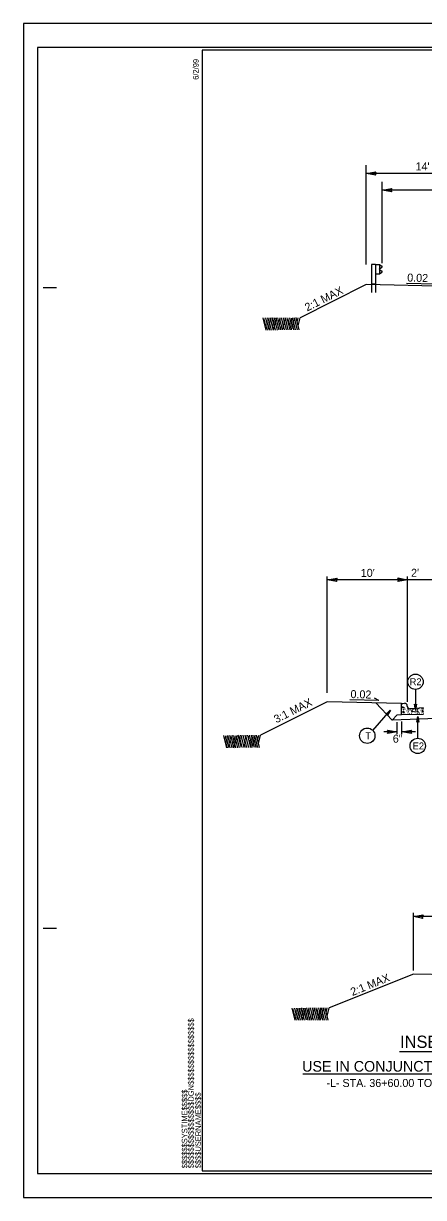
# Model space of a CAD drawing. Extents: x 573748 to 574632, y -54663 to -53209.
# Drawn here: x 573944.2 to 574019, y -53898.7 to -53678.7 of the extents above; entities that cross this region are included whole.
import ezdxf

# ---------------------------------------------------------------- set-up
doc = ezdxf.new("R2010")
doc.units = 0
for name, color, linetype in [('Prop Dimension', 7, 'Continuous'), ('Prop Dimension Text', 7, 'Continuous'), ('Prop Terminator CELL', 7, 'Continuous'), ('Sheet Cutting Line CELL', 7, 'Continuous'), ('Sheet Plot Border Inside CELL', 7, 'Continuous'), ('Sheet Plot Border Outside CELL', 7, 'Continuous'), ('Sheet Typical CELL', 7, 'Continuous'), ('Typical Arrow Superelevation CELL', 7, 'Continuous'), ('Typical Curb CELL', 7, 'Continuous'), ('Typical Guardrail CELL', 7, 'Continuous'), ('Typical Hinge Slope Arterial CELL', 7, 'Continuous'), ('Typical ID Circle CELL', 7, 'Continuous'), ('Typical Pavement Slope CELL', 7, 'Continuous'), ('Typical Slope Point Local CELL', 7, 'Continuous'), ('Typical Terminator CELL', 7, 'Continuous'), ('Typical Text General CELL', 7, 'Continuous'), ('Typical Text ID Circle CELL', 7, 'Continuous'), ('Typical Text Label CELL', 7, 'Continuous')]:
    doc.layers.add(name, color=color, linetype=linetype)

msp = doc.modelspace()

# ---------------------------------------------------------------- linework, layer by layer
at = {"layer": 'Prop Dimension'}
for p, q in [((574008.28, -53723.83), (574008.28, -53705.24)), ((574029.28, -53706.77), (574008.28, -53706.77)), ((574011.28, -53723.58), (574011.28, -53708.38)), ((574029.28, -53709.91), (574011.28, -53709.91)), ((574001.02, -53804.13), (574001.02, -53782.34)), ((574016.02, -53782.93), (574001.02, -53782.93)), ((574016.02, -53805.77), (574016.02, -53782.34)), ((574033.05, -53782.93), (574016.02, -53782.93)), ((574014.09, -53811.84), (574014.09, -53809.63)), ((574014.98, -53811.84), (574014.98, -53809.48)), ((574014.09, -53811.41), (574011.58, -53811.41)), ((574017.49, -53811.41), (574014.98, -53811.41)), ((574017.12, -53856.17), (574017.12, -53845.31)), ((574029.34, -53846.04), (574017.12, -53846.04))]:
    msp.add_line(p, q, dxfattribs=at)
at = {"layer": 'Prop Terminator CELL'}
for points in [[(574010.07, -53707.1), (574008.28, -53706.77), (574010.09, -53706.47), (574009.86, -53706.79)], [(574013.07, -53710.24), (574011.28, -53709.91), (574013.09, -53709.61), (574012.86, -53709.93)], [(574002.82, -53783.26), (574001.02, -53782.93), (574002.84, -53782.63), (574002.6, -53782.95)], [(574014.23, -53782.59), (574016.02, -53782.93), (574014.21, -53783.22), (574014.44, -53782.91)], [(574012.29, -53811.08), (574014.09, -53811.41), (574012.27, -53811.71), (574012.51, -53811.39)], [(574016.78, -53811.75), (574014.98, -53811.41), (574016.79, -53811.12), (574016.56, -53811.43)], [(574018.92, -53846.37), (574017.12, -53846.04), (574018.94, -53845.74), (574018.7, -53846.06)]]:
    msp.add_lwpolyline(points, close=True, dxfattribs=at)
at = {"layer": 'Sheet Cutting Line CELL'}
for p, q in [((574280.97, -53678.68), (573944.17, -53678.68)), ((573944.17, -53678.68), (573944.17, -53898.68)), ((573944.17, -53898.68), (574280.97, -53898.68))]:
    msp.add_line(p, q, dxfattribs=at)
at = {"layer": 'Sheet Plot Border Inside CELL'}
msp.add_lwpolyline([(574280.07, -53683.17), (573946.77, -53683.17), (573946.77, -53894.19), (574280.07, -53894.19)], close=True, dxfattribs=at)
at = {"layer": 'Sheet Plot Border Outside CELL'}
msp.add_lwpolyline([(574280.97, -53678.68), (573944.17, -53678.68), (573944.17, -53898.68), (574280.97, -53898.68)], close=True, dxfattribs=at)
at = {"layer": 'Sheet Typical CELL'}
for p, q in [((573947.87, -53728.18), (573950.37, -53728.18)), ((573947.87, -53848.18), (573950.37, -53848.18)), ((573977.57, -53893.68), (573977.57, -53893.68)), ((573977.57, -53893.68), (573977.57, -53893.68)), ((573977.57, -53893.68), (573977.57, -53893.68)), ((573977.57, -53893.68), (573977.57, -53893.68)), ((573977.57, -53893.68), (573977.57, -53893.68)), ((573977.57, -53893.68), (573977.57, -53893.68))]:
    msp.add_line(p, q, dxfattribs=at)
msp.add_lwpolyline([(574277.57, -53683.68), (573977.57, -53683.68), (573977.57, -53893.68), (574277.57, -53893.68)], close=True, dxfattribs=at)
msp.add_lwpolyline([(573985.07, -53893.68), (573985.07, -53893.68)], dxfattribs=at)
at = {"layer": 'Typical Arrow Superelevation CELL'}
for p, q in [((574021.25, -53727.53), (574015.86, -53727.38)), ((574010.63, -53805.57), (574009.85, -53805.1)), ((574010.63, -53805.57), (574005.24, -53805.43))]:
    msp.add_line(p, q, dxfattribs=at)
at = {"layer": 'Typical Curb CELL'}
for p, q in [((574014.92, -53806.1), (574015.47, -53806.08)), ((574014.92, -53808.19), (574014.92, -53806.1)), ((574015.02, -53806.89), (574015.34, -53806.78)), ((574015.31, -53806.97), (574015.02, -53806.89)), ((574015.3, -53807.55), (574015.09, -53807.71)), ((574015.44, -53807.78), (574015.3, -53807.55)), ((574015.34, -53806.78), (574015.31, -53806.97)), ((574015.99, -53806.59), (574015.99, -53806.57)), ((574019.02, -53806.91), (574016.52, -53807.08)), ((574016.85, -53807.39), (574016.79, -53807.63)), ((574017.04, -53807.63), (574016.85, -53807.39)), ((574017.92, -53807.48), (574017.71, -53807.64)), ((574018.06, -53807.72), (574017.92, -53807.48)), ((574018.8, -53807.37), (574018.74, -53807.61)), ((574018.99, -53807.62), (574018.8, -53807.37)), ((574014.09, -53808.21), (574014.92, -53808.19)), ((574014.92, -53808.19), (574019.02, -53808.09)), ((574015.09, -53807.71), (574015.44, -53807.78)), ((574016.79, -53807.63), (574017.04, -53807.63)), ((574017.71, -53807.64), (574018.06, -53807.72)), ((574018.74, -53807.61), (574018.99, -53807.62))]:
    msp.add_line(p, q, dxfattribs=at)
for centre in [(574014.96, -53806.33), (574015.08, -53806.71), (574015.29, -53807.27), (574015.41, -53806.24), (574015.54, -53807.16), (574015.92, -53807.5), (574016.08, -53807.09), (574016.12, -53807.19), (574016.19, -53807.55), (574016.49, -53807.36), (574016.55, -53807.15), (574016.96, -53807.22), (574017.16, -53807.1), (574017.39, -53807.29), (574017.5, -53807.22), (574017.55, -53807.42), (574017.91, -53807.2), (574018.16, -53807.09), (574018.54, -53807.43), (574018.7, -53807.02), (574018.74, -53807.12), (574018.97, -53807.15), (574015.28, -53808.09), (574015.64, -53807.99), (574016.01, -53808.12), (574016.12, -53807.87), (574016.37, -53808.05), (574016.8, -53807.99), (574017.14, -53808.12), (574017.23, -53807.63), (574017.43, -53807.72), (574017.57, -53808.06), (574017.9, -53808.02), (574018.25, -53807.93), (574018.63, -53808.05), (574018.74, -53807.81), (574018.98, -53807.98)]:
    msp.add_circle(centre, 0.0168, dxfattribs=at)
for centre, start, end in [((574015.48, -53806.58), 1.4804, 91.4804), ((574016.49, -53806.58), 181.4804, 273.8649)]:
    msp.add_arc(centre, 0.502, start, end, dxfattribs=at)
at = {"layer": 'Typical Guardrail CELL'}
for p, q in [((574010.05, -53723.83), (574009.3, -53723.83)), ((574009.3, -53723.83), (574009.3, -53727.56)), ((574010.05, -53723.83), (574010.05, -53727.56)), ((574010.05, -53723.83), (574010.79, -53723.83)), ((574010.79, -53723.83), (574010.79, -53725.57)), ((574010.79, -53723.83), (574011.23, -53724.14)), ((574010.05, -53725.57), (574010.79, -53725.57)), ((574010.79, -53724.63), (574011.23, -53724.33)), ((574010.79, -53724.7), (574010.79, -53724.63)), ((574010.79, -53724.7), (574010.79, -53724.77)), ((574010.79, -53724.77), (574011.23, -53725.08)), ((574010.79, -53725.57), (574011.23, -53725.27)), ((574010.05, -53727.56), (574009.3, -53727.56)), ((574009.3, -53727.56), (574009.3, -53729.07)), ((574010.05, -53727.56), (574010.05, -53729.07))]:
    msp.add_line(p, q, dxfattribs=at)
for centre, start, end in [((574011.16, -53724.23), 304.9888, 54.997), ((574011.16, -53725.17), 304.9634, 54.9941)]:
    msp.add_arc(centre, 0.116, start, end, dxfattribs=at)
at = {"layer": 'Typical Hinge Slope Arterial CELL'}
for p, q in [((574008.28, -53727.61), (573995.93, -53733.82)), ((574001.02, -53805.79), (573988.52, -53812.07)), ((574017.12, -53856.8), (574001.36, -53863.17))]:
    msp.add_line(p, q, dxfattribs=at)
at = {"layer": 'Typical ID Circle CELL'}
for p, q in [((574017.52, -53803.48), (574017.52, -53807.31)), ((574009.56, -53811.18), (574012.86, -53807.36)), ((574017.94, -53812.62), (574017.94, -53808.54))]:
    msp.add_line(p, q, dxfattribs=at)
for centre in [(574017.52, -53802.04), (574008.49, -53812.15), (574017.94, -53814.06)]:
    msp.add_circle(centre, 1.44, dxfattribs=at)
at = {"layer": 'Typical Pavement Slope CELL'}
for p, q in [((574028.18, -53728.05), (574008.28, -53727.61)), ((574014.92, -53806.1), (574001.02, -53805.79)), ((574013.13, -53809.24), (574010.11, -53805.99)), ((574013.13, -53809.24), (574014.09, -53808.21)), ((574023.19, -53808.86), (574013.13, -53809.24)), ((574028.24, -53857.04), (574017.12, -53856.8))]:
    msp.add_line(p, q, dxfattribs=at)
at = {"layer": 'Typical Slope Point Local CELL'}
for p, q in [((573989.6, -53736.14), (573989.04, -53733.84)), ((573989.25, -53734.72), (573989.46, -53733.85)), ((573989.42, -53735.41), (573989.8, -53733.85)), ((573989.58, -53736.06), (573990.13, -53733.85)), ((573989.86, -53736.14), (573990.43, -53733.85)), ((573990.59, -53736.14), (573990.23, -53734.65)), ((573990.94, -53736.14), (573990.4, -53733.97)), ((573990.95, -53734.81), (573990.71, -53733.85)), ((573990.82, -53733.92), (573990.85, -53733.82)), ((573990.87, -53735.28), (573991.22, -53733.85)), ((573990.87, -53733.96), (573990.89, -53733.85)), ((573990.93, -53734.69), (573990.95, -53734.6)), ((573990.95, -53736.14), (573991.52, -53733.85)), ((573991.68, -53736.14), (573991.32, -53734.65)), ((573991.99, -53736.1), (573991.45, -53733.93)), ((573992.33, -53736.1), (573991.76, -53733.82)), ((573991.98, -53734.66), (573992.18, -53733.82)), ((573992.14, -53735.32), (573992.51, -53733.82)), ((573992.31, -53736.03), (573992.86, -53733.82)), ((573992.65, -53736.1), (573993.21, -53733.82)), ((573993.38, -53736.1), (573993.01, -53734.62)), ((573993.72, -53736.1), (573993.19, -53733.92)), ((573994.09, -53736.1), (573993.53, -53733.82)), ((573993.74, -53734.69), (573993.95, -53733.82)), ((573993.91, -53735.35), (573994.29, -53733.82)), ((573994.06, -53735.96), (573994.32, -53734.88)), ((573994.32, -53734.88), (573994.58, -53733.82)), ((573994.32, -53736.1), (573994.89, -53733.82)), ((573995.09, -53736.1), (573994.71, -53734.54)), ((573995.42, -53736.1), (573994.87, -53733.88)), ((573995.72, -53736.1), (573995.16, -53733.8)), ((573995.37, -53734.68), (573995.58, -53733.82)), ((573995.54, -53735.37), (573995.93, -53733.82)), ((573990.24, -53736.14), (573990.05, -53735.37)), ((573991.33, -53736.14), (573991.14, -53735.37)), ((573993.03, -53736.1), (573992.84, -53735.31)), ((573994.77, -53736.1), (573994.55, -53735.2)), ((573982.2, -53814.39), (573981.63, -53812.1)), ((573981.85, -53812.97), (573982.06, -53812.1)), ((573982.02, -53813.66), (573982.4, -53812.1)), ((573982.18, -53814.32), (573982.73, -53812.1)), ((573982.46, -53814.39), (573983.03, -53812.1)), ((573982.84, -53814.39), (573982.65, -53813.62)), ((573983.19, -53814.39), (573982.83, -53812.91)), ((573983.54, -53814.39), (573983, -53812.22)), ((573983.55, -53813.07), (573983.31, -53812.1)), ((573983.42, -53812.18), (573983.45, -53812.07)), ((573983.47, -53813.54), (573983.82, -53812.1)), ((573983.47, -53812.21), (573983.49, -53812.1)), ((573983.53, -53812.94), (573983.55, -53812.86)), ((573983.55, -53814.39), (573984.12, -53812.1)), ((573983.93, -53814.39), (573983.74, -53813.62)), ((573984.28, -53814.39), (573983.92, -53812.91)), ((573984.59, -53814.35), (573984.05, -53812.18)), ((573984.93, -53814.35), (573984.36, -53812.07)), ((573984.58, -53812.92), (573984.78, -53812.07)), ((573984.74, -53813.58), (573985.11, -53812.07)), ((573984.91, -53814.29), (573985.46, -53812.07)), ((573985.25, -53814.35), (573985.81, -53812.07)), ((573985.63, -53814.35), (573985.44, -53813.56)), ((573985.98, -53814.35), (573985.61, -53812.87)), ((573986.32, -53814.35), (573985.78, -53812.18)), ((573986.69, -53814.35), (573986.13, -53812.07)), ((573986.34, -53812.94), (573986.55, -53812.07)), ((573986.5, -53813.6), (573986.89, -53812.07)), ((573986.65, -53814.21), (573986.92, -53813.14)), ((573986.92, -53813.14), (573987.18, -53812.07)), ((573986.92, -53814.35), (573987.49, -53812.07)), ((573987.37, -53814.35), (573987.15, -53813.45)), ((573987.69, -53814.35), (573987.31, -53812.8)), ((573988.02, -53814.35), (573987.47, -53812.14)), ((573988.32, -53814.35), (573987.76, -53812.06)), ((573987.97, -53812.94), (573988.18, -53812.07)), ((573988.14, -53813.62), (573988.52, -53812.07)), ((573995.03, -53865.48), (573994.47, -53863.19)), ((573994.68, -53864.07), (573994.89, -53863.2)), ((573994.85, -53864.75), (573995.23, -53863.2)), ((573995.01, -53865.41), (573995.56, -53863.2)), ((573995.29, -53865.48), (573995.86, -53863.2)), ((573995.67, -53865.48), (573995.48, -53864.72)), ((573996.02, -53865.48), (573995.66, -53864)), ((573996.37, -53865.48), (573995.83, -53863.31)), ((573996.38, -53864.16), (573996.14, -53863.2)), ((573996.25, -53863.27), (573996.28, -53863.17)), ((573996.3, -53864.63), (573996.65, -53863.2)), ((573996.3, -53863.31), (573996.32, -53863.2)), ((573996.36, -53864.04), (573996.38, -53863.95)), ((573996.38, -53865.48), (573996.95, -53863.2)), ((573996.76, -53865.48), (573996.57, -53864.72)), ((573997.11, -53865.48), (573996.75, -53864)), ((573997.42, -53865.45), (573996.88, -53863.28)), ((573997.76, -53865.45), (573997.2, -53863.17)), ((573997.41, -53864.01), (573997.61, -53863.17)), ((573997.57, -53864.67), (573997.94, -53863.17)), ((573997.74, -53865.38), (573998.29, -53863.17)), ((573998.08, -53865.45), (573998.64, -53863.17)), ((573998.46, -53865.45), (573998.27, -53864.66)), ((573998.81, -53865.45), (573998.44, -53863.96)), ((573999.16, -53865.45), (573998.62, -53863.27)), ((573999.52, -53865.45), (573998.96, -53863.17)), ((573999.17, -53864.04), (573999.38, -53863.17)), ((573999.34, -53864.69), (573999.72, -53863.17)), ((573999.49, -53865.31), (573999.75, -53864.23)), ((573999.75, -53864.23), (574000.01, -53863.17)), ((573999.75, -53865.45), (574000.32, -53863.17)), ((574000.2, -53865.45), (573999.98, -53864.55)), ((574000.52, -53865.45), (574000.14, -53863.89)), ((574000.85, -53865.45), (574000.31, -53863.23)), ((574001.16, -53865.45), (574000.59, -53863.15)), ((574000.8, -53864.03), (574001.01, -53863.17)), ((574000.97, -53864.72), (574001.36, -53863.17))]:
    msp.add_line(p, q, dxfattribs=at)
at = {"layer": 'Typical Terminator CELL'}
for points in [[(574012.04, -53808.04), (574012.86, -53807.36), (574012.31, -53808.28), (574012.26, -53808.06)], [(574017.7, -53806.25), (574017.52, -53807.31), (574017.33, -53806.25), (574017.52, -53806.38)], [(574017.76, -53809.59), (574017.94, -53808.54), (574018.13, -53809.6), (574017.94, -53809.46)]]:
    msp.add_lwpolyline(points, close=True, dxfattribs=at)
at = {"layer": 'Typical Text General CELL'}
msp.add_line((574046.27, -53875.6), (573996.45, -53875.6), dxfattribs=at)
at = {"layer": 'Typical Text Label CELL'}
msp.add_line((574028.19, -53871.37), (574014.53, -53871.37), dxfattribs=at)

# ---------------------------------------------------------------- texts
at = {"layer": 'Prop Dimension Text'}
for s, height, p in [("14'", 1.5, (574017.53, -53706.22)), ("10'", 1.5, (574007.28, -53782.38)), ("2'", 1.5, (574016.69, -53782.37)), ('6"', 1.5, (574013.27, -53813.45)), ('INSET 6A', 2.3, (574014.63, -53870.65))]:
    msp.add_text(s, height=height, dxfattribs=at).set_placement(p)
for s, rotation, p in [('0.02', 358.4883, (574015.96, -53727.04)), ('2:1 MAX', 26.6969, (573997.26, -53732.67)), ('3:1 MAX', 26.6969, (573991.48, -53809.84)), ('0.02', 358.4883, (574005.34, -53805.09)), ('2:1 MAX', 21.9988, (574005.72, -53860.94))]:
    msp.add_text(s, height=1.5, rotation=rotation, dxfattribs=at).set_placement(p)
at = {"layer": 'Sheet Typical CELL'}
for s, p in [('6/2/99', (573976.94, -53689.23)), ('$$$$$$$$$$$$$$$$DGN$$$$$$$$$$$$$$$$', (573976.04, -53893.21)), ('$$$$$$SYSTIME$$$$$', (573974.83, -53893.21)), ('$$$$USERNAME$$$$', (573977.36, -53893.21))]:
    msp.add_text(s, height=1.05, rotation=90, dxfattribs=at).set_placement(p)
at = {"layer": 'Typical Text General CELL'}
for s, height, p in [('USE IN CONJUNCTION WITH T.S. #6', 2, (573996.3, -53875.1)), ('-L- STA. 36+60.00 TO STA. 37+00.00 LT', 1.5, (574000.85, -53877.97))]:
    msp.add_text(s, height=height, dxfattribs=at).set_placement(p)
at = {"layer": 'Typical Text ID Circle CELL'}
for s, height, p in [('R2', 1.291, (574016.44, -53802.68)), ('T', 1.29, (574008.14, -53812.8)), ('E2', 1.291, (574017, -53814.71))]:
    msp.add_text(s, height=height, dxfattribs=at).set_placement(p)

doc.saveas('drawing.dxf')
